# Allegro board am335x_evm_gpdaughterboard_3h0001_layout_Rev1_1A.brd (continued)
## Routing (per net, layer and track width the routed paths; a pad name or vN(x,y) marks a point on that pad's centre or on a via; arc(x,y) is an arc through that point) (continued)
LCD_DATA12: length 169.3
  TOP w0.121: U2.30 v1(114.15,88.94) ; v2(104.33,62.12) U43.T15
  LY3 w0.121: v1(114.85,62.27) 115.03,62.45 115.03,63.08 114.85,63.27 114.85,63.69 114.79,63.75 114.79,65.29 114.98,65.48 114.98,80.57 114.72,80.83 114.72,87.86 114.15,88.43 v1(114.15,88.94)
  LY6 w0.102: 107.86,62.52 105.83,62.52 105.62,62.73 104.94,62.73 v2(104.33,62.12) 104.14,61.93 104.14,61.79 103.93,61.59 103.93,60.88 103.73,60.67 103.73,59.79 103.58,59.64
  LY6 w0.121: 107.86,62.52 109.13,62.52 109.51,62.9 113.58,62.9 114.21,62.27 v1(114.85,62.27) ; v1(34.96,55.79) 36.22,55.79 36.54,55.48 37.7,55.48 38.77,56.55 39.79,56.55 40.69,55.65 44.79,55.65 45.79,56.66 55.64,56.66 56.81,57.82 57.54,57.82 58.41,56.95 62.7,56.95 66.03,53.62 98.58,53.62 99.23,54.27 99.45,54.27 103.58,58.4 103.58,58.61 103.58,59.64
  BOTTOM w0.102: 34.91,81.44 J5.9
  BOTTOM w0.121: v1(34.96,55.79) 34.71,55.54 34.71,46.77 34.84,46.65 35.22,46.65 35.34,46.77 35.34,55.41 35.66,55.72 35.66,70.71 36.2,71.26 38.01,71.26 38.14,71.38 38.14,71.92 38.01,72.05 35.68,72.05 35.37,72.36 35.37,81.04 34.96,81.44 34.91,81.44
LCD_DATA13: length 174.5
  TOP w0.121: v2(103.33,60.13) U43.V14 ; v1(113.75,91.86) U2.29
  LY3 w0.121: v1(114.59,62.9) 114.59,63.6 114.54,63.65 114.54,69.05 113.71,69.88 113.71,89.25 113.75,89.29 v1(113.75,91.86)
  LY6 w0.102: 103.33,59.6 v2(103.33,60.13) 103.33,60.57 103.73,60.96 103.73,61.67 103.93,61.88 103.93,62.28 104.17,62.52 104.3,62.52 104.43,62.65 104.56,62.65 104.94,63.03 104.94,63.29 105.17,63.52 105.5,63.52 105.73,63.29 105.73,63.13 106.13,62.73 107.72,62.73 107.76,62.77 108.74,62.77
  LY6 w0.121: v1(36.74,55.92) 37.51,55.92 39.1,57.5 39.46,57.5 41.05,55.92 44.71,55.92 45.69,56.9 55.54,56.9 56.71,58.08 57.63,58.08 58.51,57.19 62.8,57.19 66.13,53.87 67.33,53.87 67.45,53.99 67.45,54.41 67.56,54.52 67.81,54.52 67.93,54.4 67.93,53.99 68.05,53.87 68.29,53.87 68.41,53.99 68.41,54.52 68.54,54.65 68.77,54.65 68.9,54.52 68.9,53.99 69.02,53.87 69.26,53.87 69.38,53.99 69.38,54.4 69.5,54.52 69.74,54.52 69.86,54.4 69.86,54.27 69.99,54.14 98.75,54.14 99.13,54.52 99.35,54.52 103.33,58.5 103.33,59.6 ; 108.74,62.77 109.38,63.41 114.08,63.41 v1(114.59,62.9)
  BOTTOM w0.102: J6.10 36.61,81.44 36.49,81.32
  BOTTOM w0.121: v1(36.74,55.92) 36.74,57.57 37.05,57.88 37.05,58.46 37.18,58.58 42.71,58.58 42.84,58.71 42.84,62.14 42.71,62.27 37.18,62.27 37.05,62.39 37.05,70.14 37.18,70.26 39.92,70.26 40.04,70.39 40.04,72.05 40.17,72.17 43.73,72.17 43.85,72.3 43.85,73.32 43.73,73.44 43.34,73.44 43.22,73.57 43.22,74.21 43.09,74.33 39.02,74.33 38.95,74.39 36.49,74.39 36.36,74.52 36.36,81.19 36.49,81.32
LCD_DATA14: length 173.4
  TOP w0.121: v1(112.95,91.72) U2.27 ; v2(104.33,60.13) U43.V15
  LY3 w0.121: v1(114.72,61.38) 114.15,61.95 114.15,69.09 113.4,69.84 113.4,78.76 112.75,79.41 112.75,89.25 112.95,89.46 v1(112.95,91.72)
  LY6 w0.102: 107.86,61.38 107.72,61.52 105.94,61.52 105.73,61.73 105.04,61.73 104.74,61.43 104.74,60.97 104.33,60.57 v2(104.33,60.13) 104.33,59.6
  LY6 w0.121: 104.33,59.6 104.33,58.36 99.67,53.69 99.41,53.69 98.84,53.12 65.06,53.12 61.73,56.45 56.77,56.45 56.43,56.11 45.95,56.11 45.51,55.67 45.51,55.67 44.99,55.15 44.58,55.15 44.58,55.16 41.44,55.16 41.31,55.03 41.31,54.52 41.19,54.39 39.98,54.39 39.85,54.52 39.85,55.16 39.72,55.28 39.09,55.28 38.97,55.16 38.97,54.52 38.84,54.39 35.16,54.39 35.04,54.51 35.04,55.16 34.92,55.28 34.68,55.28 34.56,55.16 34.56,54.51 34.44,54.39 34.2,54.39 34.08,54.51 34.08,55.16 33.96,55.28 33.72,55.28 33.59,55.16 33.59,54.51 33.47,54.39 31.15,54.39 31.03,54.52 31.03,55.28 31.15,55.41 v1(32.8,55.41) ; v1(114.72,61.38) 107.86,61.38
  BOTTOM w0.102: J5.12 31.95,80.17 31.69,79.92
  BOTTOM w0.121: 31.69,79.92 31.69,74.08 31.82,73.95 33.44,73.95 33.57,73.82 33.57,73.38 33.69,73.26 34.33,73.26 34.46,73.13 34.46,71.18 34.84,70.81 34.84,68.83 34.71,68.71 34.27,68.71 34.14,68.58 34.14,68.03 34.45,67.71 34.45,67.41 34.14,67.09 34.14,66.73 34.45,66.41 34.45,66.15 34.1,65.79 34.1,65.57 33.97,65.44 31.28,65.44 31.15,65.32 31.15,64.04 31.35,63.84 32.12,63.84 32.68,63.28 34.71,63.28 34.84,63.16 34.84,60.74 34.71,60.62 32.68,60.62 32.55,60.49 32.55,60.11 32.68,59.98 34.71,59.98 34.84,59.85 34.84,58.97 34.71,58.84 32.93,58.84 32.8,58.71 v1(32.8,55.41)
LCD_DATA15: length 169.7
  TOP w0.102: U43.V17 v2(106.34,60.13)
  TOP w0.121: U2.26 112.55,89.06 v1(112.31,88.81)
  LY3 w0.121: v1(112.31,88.81) 112.31,88.18 112.5,87.98 112.5,79.31 113.15,78.66 113.15,69.74 113.9,68.99 113.9,61.84 114.08,61.66 v1(114.08,58.97)
  LY6 w0.102: 107.86,59.6 106.84,59.6 106.34,60.11 ; 105.83,59.09 105.83,59.6 106.34,60.11 ; 106.34,60.11 v2(106.34,60.13)
  LY6 w0.121: v1(114.08,58.97) 111.67,58.97 111.04,59.6 107.86,59.6 ; v1(46.65,54.9) 46.65,54.52 46.77,54.39 56.17,54.39 57.44,55.66 61,55.66 62.27,54.39 62.27,52.9 63.06,52.11 104.3,52.11 105.83,53.63 105.83,59.09
  BOTTOM w0.102: J6.7 39.36,82.71
  BOTTOM w0.121: v1(46.65,54.9) 46.65,53.89 46.77,53.76 49.82,53.76 49.95,53.89 49.95,82.78 49.82,82.91 48.79,82.91 48.66,82.79 48.66,82.59 48.54,82.46 48.31,82.46 48.18,82.59 48.18,82.79 48.06,82.91 47.82,82.91 47.7,82.79 47.7,82.07 47.58,81.95 47.34,81.95 47.22,82.07 47.22,82.79 47.1,82.91 46.86,82.91 46.73,82.79 46.73,82.07 46.61,81.95 46.37,81.95 46.25,82.07 46.25,82.79 46.13,82.91 45.89,82.91 45.77,82.79 45.77,82.07 45.65,81.95 45.41,81.95 45.29,82.07 45.29,82.79 45.17,82.91 44.92,82.91 44.8,82.79 44.8,82.07 44.68,81.95 43.6,81.95 43.47,82.08 43.47,83 42.49,83.98 40.68,83.98 40.55,83.86 40.55,82.97 40.42,82.84 40.17,82.84 40.04,82.97 40.04,85.38 39.92,85.51 39.66,85.51 39.53,85.38 39.53,82.84 39.41,82.71 39.36,82.71
LCD_DEN: length 129.2
  TOP w0.121: v2(99.34,60.13) U43.V10
  LY6 w0.102: v2(99.34,60.13) 99.34,59.97 98.97,59.6
  LY6 w0.121: 98.97,59.6 98.72,59.35 87.03,59.35 86.91,59.47 86.91,59.73 86.78,59.85 86.4,59.85 86.27,59.73 86.27,59.47 86.14,59.35 85.89,59.35 85.76,59.47 85.76,59.73 85.64,59.85 85.39,59.85 85.27,59.73 85.27,59.47 85.15,59.35 84.9,59.35 84.78,59.47 84.78,61 84.66,61.12 84.42,61.12 84.3,61 84.3,59.47 84.18,59.35 83.94,59.35 83.82,59.47 83.82,61 83.7,61.12 83.46,61.12 83.34,61 83.34,59.47 83.22,59.35 82.97,59.35 82.85,59.47 82.85,61 82.73,61.12 82.49,61.12 82.37,61 82.37,59.47 82.25,59.35 82.01,59.35 81.89,59.47 81.89,61 81.77,61.12 81.53,61.12 81.41,61 81.41,59.47 81.29,59.35 81.04,59.35 80.92,59.47 80.92,61 80.8,61.12 80.56,61.12 80.44,61 80.44,60.11 80.31,59.98 80.09,59.98 79.96,60.11 79.96,61 79.84,61.12 50.01,61.12 49.82,61.31 43.98,61.31 43.92,61.25 v1(43.85,61.25)
  BOTTOM w0.102: 39.36,76.36 J6.17
  BOTTOM w0.121: 39.36,76.36 39.79,76.36 39.92,76.24 39.92,74.97 40.04,74.84 41.19,74.84 41.31,74.97 41.31,80.17 41.58,80.44 48.3,80.44 48.42,80.31 48.42,64.68 48.3,64.55 48.05,64.55 47.93,64.67 47.93,66.34 47.81,66.46 47.57,66.46 47.45,66.34 47.45,64.67 47.33,64.55 47.08,64.55 46.96,64.67 46.96,66.34 46.84,66.46 46.6,66.46 46.48,66.34 46.48,64.67 46.36,64.55 46.12,64.55 46,64.67 46,66.34 45.88,66.46 45.64,66.46 45.52,66.34 45.52,64.67 45.4,64.55 45.15,64.55 45.03,64.67 45.03,66.34 44.91,66.46 44.67,66.46 44.55,66.34 44.55,64.67 44.43,64.55 43.98,64.55 43.85,64.43 v1(43.85,61.25)
LCD_HSYNC: length 129
  TOP w0.121: v2(101.34,60.13) U43.V12
  LY6 w0.102: v2(101.34,60.13) 101.34,59.6
  LY6 w0.121: 101.34,59.6 101.34,58.79 100.37,57.83 83.05,57.83 82.5,57.28 82.17,57.28 82.05,57.4 82.05,57.71 81.93,57.83 81.69,57.83 81.56,57.71 81.56,57.4 81.44,57.28 81.2,57.28 81.08,57.4 81.08,57.71 80.96,57.83 80.72,57.83 80.6,57.71 80.6,57.4 80.48,57.28 80.24,57.28 80.12,57.4 80.12,57.71 80,57.83 79.75,57.83 79.63,57.71 79.63,57.4 79.51,57.28 79.27,57.28 79.15,57.4 79.15,57.71 79.03,57.83 78.79,57.83 78.67,57.71 78.67,57.4 78.55,57.28 78.31,57.28 78.19,57.4 78.19,57.71 78.07,57.83 77.82,57.83 77.7,57.71 77.7,57.4 77.58,57.28 77.34,57.28 77.22,57.4 77.22,57.71 77.1,57.83 76.86,57.83 76.74,57.71 76.74,57.4 76.62,57.28 76.38,57.28 76.26,57.4 76.26,57.71 76.14,57.83 75.89,57.83 75.77,57.71 75.77,57.4 75.65,57.28 75.41,57.28 75.29,57.4 75.29,57.71 75.17,57.83 74.93,57.83 74.81,57.71 74.81,57.4 74.69,57.28 74.45,57.28 74.33,57.4 74.33,57.71 74.2,57.83 73.96,57.83 73.84,57.71 73.84,57.4 73.72,57.28 73.48,57.28 73.36,57.4 73.36,57.71 73.24,57.83 73,57.83 72.88,57.71 72.88,57.4 72.76,57.28 64.82,57.28 63.42,58.68 60.01,58.68 59.09,59.6 55.79,59.6 55.66,59.47 55.66,59.13 55.5,58.97 55.32,58.97 55.03,59.26 55.03,59.47 54.9,59.6 47.22,59.6 47.09,59.47 47.09,58.58 46.97,58.46 44.61,58.46 v1(44.36,58.71)
  BOTTOM w0.102: 39.36,75.73 37.88,75.73 J6.18
  BOTTOM w0.121: 39.36,75.73 39.53,75.73 39.66,75.6 39.66,74.71 39.79,74.59 41.43,74.59 41.56,74.71 41.56,79.79 41.97,80.19 48.04,80.19 48.17,80.07 48.17,67.22 48.04,67.09 47.8,67.09 47.67,67.21 47.67,68.49 47.55,68.62 47.32,68.62 47.19,68.49 47.19,67.21 47.07,67.09 46.83,67.09 46.71,67.21 46.71,68.62 46.59,68.74 46.35,68.74 46.23,68.62 46.23,67.21 46.11,67.09 45.86,67.09 45.74,67.21 45.74,68.62 45.62,68.74 45.38,68.74 45.26,68.62 45.26,67.21 45.14,67.09 44.9,67.09 44.78,67.21 44.78,68.62 44.66,68.74 44.42,68.74 44.3,68.62 44.3,67.21 44.18,67.09 43.22,67.09 43.09,66.97 43.09,59.15 43.22,59.03 43.4,59.03 43.53,59.15 43.53,59.73 43.65,59.85 44.23,59.85 44.36,59.73 v1(44.36,58.71)
LCD_PCLK: length 129.1
  TOP w0.121: v2(100.34,60.13) U43.V11
  LY6 w0.102: 100.34,59.6 v2(100.34,60.13)
  LY6 w0.121: 100.34,59.6 100.34,59.03 99.89,58.58 72.68,58.58 72.55,58.71 72.55,60.24 72.43,60.36 72.15,60.36 72.03,60.24 72.03,58.7 71.91,58.58 71.66,58.58 71.54,58.7 71.54,60.24 71.42,60.36 71.18,60.36 71.06,60.24 71.06,58.7 70.94,58.58 70.7,58.58 70.58,58.7 70.58,60.24 70.46,60.36 70.22,60.36 70.1,60.24 70.1,58.7 69.98,58.58 69.73,58.58 69.61,58.7 69.61,60.24 69.49,60.36 69.25,60.36 69.13,60.24 69.13,59.09 69,58.97 68.78,58.97 68.65,59.09 68.65,60.24 68.53,60.36 46.77,60.36 46.58,60.17 44.52,60.17 44.49,60.2 v1(44.49,60.24)
  BOTTOM w0.102: 39.36,77 37.88,77 J6.16
  BOTTOM w0.121: 39.36,77 39.98,77 40.11,76.87 40.11,76.39 40.16,76.34 40.16,75.22 40.29,75.09 40.92,75.09 41.05,75.22 41.05,80.42 41.34,80.71 48.4,80.71 48.69,80.42 48.69,61.89 48.56,61.76 48.04,61.76 47.92,61.89 47.92,64.17 47.79,64.3 47.41,64.3 47.28,64.17 47.28,62.01 47.15,61.89 46.65,61.89 46.52,62.01 46.52,64.17 46.39,64.3 46.01,64.3 45.88,64.17 45.88,62.01 45.76,61.89 45.25,61.89 45.12,62.01 45.12,64.17 45,64.3 44.61,64.3 44.49,64.17 v1(44.49,60.24)
LCD_VSYNC: length 129.1
  TOP w0.121: v2(102.33,60.13) U43.V13
  LY6 w0.102: v2(102.33,60.13) 102.33,59.6
  LY6 w0.121: 102.33,59.6 102.33,58.62 100.27,56.55 97.36,56.55 97.11,56.81 96.88,56.81 96.75,56.68 96.75,56.65 96.63,56.53 96.39,56.53 96.27,56.65 96.27,56.96 96.15,57.08 95.91,57.08 95.79,56.96 95.79,56.65 95.67,56.53 95.42,56.53 95.3,56.65 95.3,56.96 95.18,57.08 94.94,57.08 94.82,56.96 94.82,56.65 94.7,56.53 94.46,56.53 94.34,56.65 94.34,56.96 94.22,57.08 93.98,57.08 93.86,56.96 93.86,56.65 93.74,56.53 93.49,56.53 93.37,56.65 93.37,56.96 93.25,57.08 93.01,57.08 92.89,56.96 92.89,56.65 92.77,56.53 92.53,56.53 92.41,56.65 92.41,56.96 92.29,57.08 92.05,57.08 91.93,56.96 91.93,56.65 91.81,56.53 91.56,56.53 91.44,56.65 91.44,56.96 91.32,57.08 91.08,57.08 90.96,56.96 90.96,56.65 90.84,56.53 90.6,56.53 90.48,56.65 90.48,56.96 90.36,57.08 90.12,57.08 90,56.96 90,56.65 89.87,56.53 89.63,56.53 89.51,56.65 89.51,56.96 89.39,57.08 89.15,57.08 89.03,56.96 89.03,56.65 88.91,56.53 88.67,56.53 88.55,56.65 88.55,56.96 88.43,57.08 88.19,57.08 88.06,56.96 88.06,56.65 87.94,56.53 87.7,56.53 87.58,56.65 87.58,56.96 87.46,57.08 87.22,57.08 87.1,56.96 87.1,56.65 86.98,56.53 86.74,56.53 86.62,56.65 86.62,56.96 86.5,57.08 86.26,57.08 86.13,56.96 86.13,56.65 86.01,56.53 85.77,56.53 85.65,56.65 85.65,56.96 85.53,57.08 85.29,57.08 85.17,56.96 85.17,56.65 85.05,56.53 84.81,56.53 84.69,56.65 84.69,56.96 84.57,57.08 84.32,57.08 84.2,56.96 84.2,56.65 84.08,56.53 83.84,56.53 83.72,56.65 83.72,56.96 83.6,57.08 83.36,57.08 83.24,56.96 83.24,56.65 83.12,56.53 64.51,56.53 63.11,57.94 59.1,57.94 58.2,58.84 56.42,58.84 55.23,57.65 51.73,57.65 51.47,57.9 51.47,58.46 51.09,58.84 48.81,58.84 48.42,58.46 48.42,57.9 48.17,57.65 44.31,57.65 43.73,57.06 41.54,57.06 40.35,58.24 38.56,58.24 37.76,57.44 35.6,57.44 v1(35.22,57.82)
  BOTTOM w0.102: J5.17 34.84,76.36 34.91,76.29
  BOTTOM w0.121: 34.91,76.29 35.12,76.08 35.12,72.26 35.58,71.8 35.98,71.8 36.11,71.67 36.11,71.51 35.75,71.15 35.54,71.15 35.41,71.02 35.41,70.81 35.41,58.78 34.71,58.08 34.71,57.19 34.07,56.55 34.07,47.28 34.2,47.15 34.33,47.15 34.46,47.28 34.46,55.92 34.59,56.05 34.6,56.05 35.22,56.67 v1(35.22,57.82)
LCDA_PIN18: length 5.2
  TOP w0.102: 32.03,76.36 J5.18
  TOP w0.121: 32.03,76.36 31.79,76.12 31.79,73.57 32.42,72.94 R13.2
LCDBD_D0: length 74.3
  TOP w0.121: v2(106.34,63.13) U43.R17
  LY3 w0.102: v2(106.34,63.13) 106.74,62.72 107.41,62.72 107.86,62.27 107.86,61.76
  LY3 w0.121: 107.86,61.76 108.11,61.51 108.11,58.58 107.73,58.2 107.73,37.12 105.19,34.58 105.19,32.93 103.8,31.53 v1(103.8,26.71)
  LY6 w0.121: v1(103.8,26.71) 103.29,26.2 78.78,26.2 77.76,27.22 77.76,28.08 77.88,28.21 78.28,28.21 78.4,28.33 78.4,28.57 78.28,28.69 77.88,28.69 77.76,28.81 77.76,29.05 77.88,29.17 78.28,29.17 78.4,29.29 78.4,29.53 78.28,29.65 77.88,29.65 77.76,29.77 J19.4
LCDBD_D1: length 74.2
  TOP w0.121: v2(105.34,63.13) U43.R16
  LY3 w0.102: 107.73,59.6 107.73,61.38 107.48,61.63 107.23,61.63 106.84,62.01 106.84,62.17 106.5,62.52 105.94,62.52 v2(105.34,63.13)
  LY3 w0.121: 107.73,59.6 107.73,58.84 107.48,58.58 107.48,38.26 106.59,37.38 106.59,36.36 104.94,34.71 104.94,33.06 102.91,31.03 v1(102.91,26.71)
  LY6 w0.095: 78.4,32.17 78.4,33.44
  LY6 w0.121: v1(102.91,26.71) 81.31,26.71 81.19,26.83 81.19,27.48 81.07,27.6 80.83,27.6 80.71,27.48 80.71,26.83 80.59,26.71 78.78,26.71 78.4,27.09 78.4,27.98 78.64,28.22 78.64,29.63 78.4,29.88 78.4,32.17 ; 78.4,33.44 J19.3
LCDBD_D2: length 74.5
  TOP w0.121: v2(106.34,64.13) U43.P17
  LY3 w0.102: 107.86,63.72 106.79,63.72 106.38,64.13 v2(106.34,64.13)
  LY3 w0.121: 107.86,63.72 108.29,63.72 108.88,63.14 108.88,61.76 109.51,61.12 109.51,41.06 108.88,40.42 108.88,37.12 106.97,35.22 106.97,33.95 104.94,31.91 v1(104.94,27.22)
  LY6 w0.121: J19.6 79.03,31.28 83.35,26.96 84.38,26.96 84.5,27.08 84.5,27.23 84.62,27.35 84.86,27.35 84.98,27.23 84.98,27.08 85.1,26.96 85.34,26.96 85.46,27.08 85.46,27.23 85.58,27.35 85.83,27.35 85.95,27.23 85.95,27.08 86.07,26.96 86.31,26.96 86.43,27.08 86.43,27.23 86.55,27.35 86.79,27.35 86.91,27.23 86.91,27.08 87.03,26.96 87.27,26.96 87.39,27.08 87.39,27.23 87.51,27.35 87.76,27.35 87.88,27.23 87.88,27.08 88,26.96 88.24,26.96 88.36,27.08 88.36,27.23 88.48,27.35 88.72,27.35 88.84,27.23 88.84,27.08 88.96,26.96 89.2,26.96 89.32,27.08 89.32,27.23 89.44,27.35 89.69,27.35 89.81,27.23 89.81,27.08 89.93,26.96 90.17,26.96 90.29,27.08 90.29,27.23 90.41,27.35 90.65,27.35 90.77,27.23 90.77,27.08 90.89,26.96 102.15,26.96 102.4,27.22 v1(104.94,27.22)
LCDBD_D3: length 74
  TOP w0.121: v2(105.34,64.13) U43.P16
  LY3 w0.102: 107.86,63.41 107.75,63.52 105.97,63.52 105.37,64.13 v2(105.34,64.13)
  LY3 w0.121: v1(104.43,27.92) 104.43,31.79 106.65,34.01 106.65,35.34 108.23,36.92 108.23,36.98 108.62,37.38 108.62,40.55 109.26,41.19 109.26,60.62 108.62,61.25 108.62,62.9 108.11,63.41 107.86,63.41
  LY6 w0.095: 79.67,32.17 79.67,33.44
  LY6 w0.121: 79.67,32.17 79.67,31.5 83.57,27.6 91.81,27.6 91.93,27.48 91.93,27.33 92.05,27.21 92.3,27.21 92.42,27.33 92.42,27.48 92.54,27.6 92.78,27.6 92.9,27.48 92.9,27.33 93.02,27.21 93.26,27.21 93.38,27.33 93.38,27.48 93.5,27.6 93.74,27.6 93.86,27.48 93.86,27.33 93.98,27.21 94.23,27.21 94.35,27.33 94.35,27.48 94.47,27.6 94.71,27.6 94.83,27.48 94.83,27.33 94.95,27.21 95.19,27.21 95.31,27.33 95.31,27.48 95.43,27.6 95.67,27.6 95.79,27.48 95.79,27.33 95.91,27.21 96.16,27.21 96.28,27.33 96.28,27.48 96.4,27.6 96.64,27.6 96.76,27.48 96.76,27.33 96.88,27.21 97.12,27.21 97.24,27.33 97.24,27.48 97.36,27.6 104.11,27.6 v1(104.43,27.92) ; 79.67,33.44 J19.5
LCDBD_D4: length 74.5
  TOP w0.121: v2(107.34,65.13) U43.N18
  LY3 w0.102: v2(107.34,65.13) 107.86,65.13
  LY3 w0.121: v1(106.34,28.36) 106.34,32.04 110.03,35.73 110.03,40.05 110.82,40.85 110.82,62.73 108.5,65.06 108.11,65.06 108.05,65.13 107.86,65.13
  LY6 w0.121: J19.8 80.3,31.28 83.73,27.85 87.29,27.85 87.41,27.98 87.41,28.23 87.54,28.36 87.96,28.36 88.08,28.24 88.08,27.96 88.2,27.84 88.44,27.84 88.56,27.96 88.56,28.24 88.68,28.36 88.92,28.36 89.04,28.24 89.04,27.96 89.16,27.84 89.4,27.84 89.52,27.96 89.52,28.24 89.64,28.36 89.89,28.36 90.01,28.24 90.01,27.96 90.13,27.84 90.37,27.84 90.49,27.96 90.49,28.24 90.61,28.36 90.85,28.36 90.97,28.24 90.97,27.96 91.09,27.84 91.33,27.84 91.45,27.96 91.45,28.24 91.58,28.36 91.82,28.36 91.94,28.24 91.94,27.96 92.06,27.84 92.3,27.84 92.42,27.96 92.42,28.24 92.54,28.36 v1(106.34,28.36)
LCDBD_D5: length 74.1
  TOP w0.121: v2(106.34,65.13) U43.N17
  LY3 w0.102: 107.86,64.71 107.6,64.71 107.58,64.72 106.82,64.72 106.42,65.13 v2(106.34,65.13)
  LY3 w0.121: v1(105.57,28.99) 105.57,31.79 109.78,35.99 109.78,40.18 110.57,40.98 110.57,62.6 108.47,64.71 107.86,64.71
  LY6 w0.095: 80.94,32.17 80.94,33.44
  LY6 w0.121: v1(105.57,28.99) 105.57,28.73 105.45,28.61 89.77,28.61 89.65,28.73 89.65,29 89.53,29.12 89.29,29.12 89.17,29 89.17,28.73 89.05,28.61 88.81,28.61 88.69,28.73 88.69,29 88.57,29.12 88.33,29.12 88.21,29 88.21,28.73 88.08,28.61 87.41,28.61 87.28,28.73 87.28,29.12 87.15,29.25 86.59,29.25 86.46,29.12 86.46,28.23 86.34,28.1 83.83,28.1 80.94,30.99 80.94,32.17 ; 80.94,33.44 J19.7
LCDBD_D6: length 74.4
  TOP w0.121: v2(105.34,65.13) U43.N16
  LY3 w0.102: 107.75,64.47 107.55,64.47 107.5,64.52 105.86,64.52 105.34,65.05 v2(105.34,65.13)
  LY3 w0.121: 107.75,64.47 107.79,64.43 108.37,64.43 110.27,62.52 110.27,41.03 109.53,40.28 109.53,36.39 v1(108.17,35.03)
  LY6 w0.121: 85.38,38.52 85.38,39.52 85.53,39.67 88.42,39.67 89.19,38.9 97.7,38.9 97.95,38.65 97.95,37.76 98.08,37.63 99.52,37.63 99.64,37.76 99.64,38.14 99.76,38.26 100,38.26 100.12,38.14 100.12,36.48 100.25,36.36 100.49,36.36 100.61,36.48 100.61,38.14 100.73,38.26 100.97,38.26 101.09,38.14 101.09,36.48 101.21,36.36 101.45,36.36 101.57,36.48 101.57,38.14 101.69,38.26 101.93,38.26 102.06,38.14 102.06,36.48 102.18,36.36 102.42,36.36 102.54,36.48 102.54,38.14 102.66,38.26 102.9,38.26 103.02,38.14 103.02,36.48 103.14,36.36 107.99,36.36 108.11,36.23 108.11,35.09 v1(108.17,35.03)
LCDBD_D7: length 74.2
  TOP w0.121: v2(107.34,66.13) U43.M18
  LY3 w0.102: 107.86,66.13 v2(107.34,66.13)
  LY3 w0.121: 107.86,66.13 108.07,66.13 108.11,66.08 108.5,66.08 108.63,65.94 108.7,65.94 111.57,63.07 111.57,40 v1(111.22,39.66)
  LY6 w0.121: v1(111.22,39.66) 110.13,39.66 109.77,39.29 98.71,39.29 98.11,39.89 94.92,39.89 94.8,40.01 94.8,41.19 94.67,41.31 94.44,41.31 94.31,41.19 94.31,40.01 94.19,39.89 93.95,39.89 93.83,40.01 93.83,41.19 93.71,41.31 93.48,41.31 93.35,41.19 93.35,40.01 93.23,39.89 92.99,39.89 92.87,40.01 92.87,41.06 92.75,41.19 92.51,41.19 92.38,41.06 92.38,40.01 92.26,39.89 92.02,39.89 91.9,40.01 91.9,41.06 91.78,41.19 91.54,41.19 91.42,41.06 91.42,40.01 91.3,39.89 91.06,39.89 90.94,40.01 90.94,41.06 90.82,41.19 90.57,41.19 90.45,41.06 90.45,40.01 90.33,39.89 89.7,39.89 88.85,40.74 81.89,40.74 81.57,40.42 81.57,38.52
LCDBD_D8: length 74.5
  TOP w0.121: v2(106.34,66.13) U43.M17
  LY3 w0.102: v2(106.34,66.13) 106.42,66.13 106.81,65.73 107.7,65.73 107.77,65.66 107.86,65.66
  LY3 w0.121: v1(111.04,37.12) 110.78,37.38 110.78,40.04 111.32,40.58 111.32,62.97 108.6,65.69 108.5,65.69 108.5,65.7 107.99,65.7 107.95,65.66 107.86,65.66
  LY6 w0.121: v1(111.04,37.12) 110.53,37.12 110.27,36.87 109.68,36.87 109.56,36.99 109.56,38.4 109.44,38.52 109.2,38.52 109.08,38.4 109.08,36.99 108.96,36.87 108.72,36.87 108.6,36.99 108.6,38.4 108.48,38.52 108.23,38.52 108.11,38.4 108.11,36.99 107.99,36.87 107.75,36.87 107.63,36.99 107.63,38.4 107.51,38.52 107.27,38.52 107.15,38.4 107.15,36.99 107.03,36.87 106.72,36.87 106.46,37.12 106.46,38.23 106.18,38.51 103.35,38.51 103.1,38.77 99.5,38.77 99.15,38.41 98.58,38.41 98.45,38.54 98.45,38.85 97.91,39.39 89.43,39.39 88.66,40.16 83.1,40.16 82.84,39.91 J20.11
LCDBD_D9: length 74.5
  TOP w0.121: v2(105.34,66.13) U43.M16
  LY3 w0.102: v2(105.34,66.13) 105.34,66.06 105.88,65.52 107.57,65.52 107.67,65.42 108.06,65.42 108.08,65.44
  LY3 w0.121: 108.08,65.44 108.5,65.44 111.07,62.87 111.07,40.71 110.27,39.92 110.27,37.12 110.53,36.87 v1(110.53,36.23)
  LY6 w0.121: v1(110.53,36.23) 110.53,36.49 110.4,36.61 106.32,36.61 106.2,36.73 106.2,38.14 106.08,38.26 105.83,38.26 105.71,38.14 105.71,36.73 105.59,36.61 105.35,36.61 105.23,36.73 105.23,38.14 105.11,38.26 104.87,38.26 104.75,38.14 104.75,36.73 104.63,36.61 104.39,36.61 104.27,36.73 104.27,38.14 104.15,38.26 103.9,38.26 103.78,38.14 103.78,36.73 103.66,36.61 103.42,36.61 103.27,36.76 103.27,38.25 103,38.52 99.61,38.52 99.25,38.16 98.47,38.16 98.2,38.43 98.2,38.75 97.8,39.15 89.32,39.15 88.56,39.92 84.62,39.92 84.11,39.41 84.11,38.52
LCDBD_D10: length 74.2
  TOP w0.121: v2(107.34,67.13) U43.L18
  LY3 w0.102: 107.71,67.13 v2(107.34,67.13)
  LY3 w0.121: 107.71,67.13 108.59,67.13 112.31,63.41 112.31,35.73 108.75,32.17 108.75,31.35 108.3,30.9 108.3,28.49 108.17,28.36 107.48,28.36 107.35,28.49 v1(107.35,29.88)
  LY6 w0.121: 81.57,32.8 81.57,31.53 82.78,30.33 107.23,30.33 107.35,30.2 v1(107.35,29.88)
LCDBD_D11: length 74.3
  TOP w0.121: v2(106.34,67.13) U43.L17
  LY3 w0.102: v2(106.34,67.13) 106.78,67.13 107.17,67.52 107.5,67.52 107.5,67.52 107.77,67.52
  LY3 w0.121: v1(109.26,32.04) 112.56,35.34 112.56,63.54 108.58,67.52 107.77,67.52
  LY6 w0.121: v1(109.26,32.04) 112.05,32.04 112.18,32.17 112.18,33.06 112.05,33.18 88.81,33.18 88.68,33.06 88.68,32.04 88.56,31.91 85.51,31.91 85.38,32.04 85.38,32.8
LCDBD_D12: length 74.3
  TOP w0.121: v2(105.34,67.13) U43.L16
  LY3 w0.102: v2(105.34,67.13) 105.78,67.13 106.17,67.52 106.25,67.52 106.47,67.73 107.62,67.73 107.73,67.85
  LY3 w0.121: v1(108.75,30.65) 108.76,30.65 112.8,34.7 112.8,63.67 108.63,67.85 107.73,67.85
  LY6 w0.095: 82.21,32.17 82.21,33.44
  LY6 w0.121: 82.21,33.44 81.57,34.07 ; v1(108.75,30.65) 83.72,30.65 82.21,32.17
LCDBD_D13: length 74.2
  TOP w0.121: v2(107.34,68.13) U43.K18
  LY3 w0.102: 107.86,68.13 v2(107.34,68.13)
  LY3 w0.121: 107.86,68.13 107.91,68.13 108.02,68.24 108.62,68.24 113.05,63.81 113.05,40.44 113.32,40.17 v1(113.32,37.76)
  LY6 w0.095: 82.21,39.15 82.21,37.88
  LY6 w0.121: v1(113.32,37.76) 112.43,37.76 112.31,37.88 112.31,38.65 112.18,38.77 111.67,38.77 111.54,38.65 111.54,37.88 111.42,37.76 111.04,37.76 110.92,37.88 110.92,38.77 110.79,38.9 110.56,38.9 110.43,38.77 110.43,37.88 110.31,37.76 110.02,37.76 109.89,37.88 109.89,38.92 109.77,39.04 98.61,39.04 98.01,39.64 89.53,39.64 88.76,40.41 82.57,40.41 82.21,40.04 82.21,39.15 ; 82.21,37.88 81.57,37.25
LCDBD_D14: length 74.1
  TOP w0.121: v2(106.34,68.13) U43.K17
  LY3 w0.102: 107.86,68.55 106.76,68.55 v2(106.34,68.13)
  LY3 w0.121: 107.86,68.55 108.69,68.55 113.3,63.94 113.3,40.65 113.76,40.19 113.76,32.74 112.18,31.15 v1(110.53,31.15)
  LY6 w0.121: J19.12 82.84,32.04 83.98,30.9 108.11,30.9 108.37,31.15 v1(110.53,31.15)
LCDBD_D15: length 74.5
  TOP w0.121: v2(105.34,68.13) U43.K16
  LY3 w0.102: 107.99,68.87 106.08,68.87 v2(105.34,68.13)
  LY3 w0.121: v1(114.08,41.44) 113.7,41.44 113.55,41.59 113.55,64.96 109.7,68.81 108.44,68.81 108.38,68.87 107.99,68.87
  LY6 w0.121: v1(114.08,41.44) 105.16,41.44 105.04,41.32 105.04,40.8 104.92,40.68 104.68,40.68 104.56,40.8 104.56,41.32 104.44,41.44 104.2,41.44 104.08,41.32 104.08,40.8 103.95,40.68 103.71,40.68 103.59,40.8 103.59,41.32 103.47,41.44 96.56,41.44 96.11,41.89 80.56,41.89 80.3,41.64 J20.7
LCDBD_D16: length 74.4
  TOP w0.121: v2(104.33,63.13) U43.R15
  LY3 w0.102: 104.62,59.6 104.62,59.74 104.74,59.85 104.74,62.53 104.53,62.73 104.53,62.93 v2(104.33,63.13)
  LY3 w0.121: v1(104.62,39.79) 104.62,59.6
  LY6 w0.095: 80.94,39.15 80.94,37.88
  LY6 w0.121: 80.94,39.15 80.94,41.31 81.27,41.64 82.6,41.64 82.72,41.52 82.72,41.11 82.84,40.99 83.08,40.99 83.2,41.11 83.2,41.52 83.33,41.64 83.57,41.64 83.69,41.52 83.69,41.11 83.81,40.99 84.05,40.99 84.17,41.11 84.17,41.52 84.29,41.64 84.53,41.64 84.65,41.52 84.65,41.11 84.77,40.99 85.01,40.99 85.13,41.11 85.13,41.52 85.26,41.64 85.5,41.64 85.62,41.52 85.62,41.11 85.74,40.99 85.98,40.99 86.1,41.11 86.1,41.52 86.22,41.64 86.46,41.64 86.58,41.52 86.58,41.11 86.7,40.99 86.94,40.99 87.07,41.11 87.07,41.52 87.19,41.64 87.43,41.64 87.55,41.52 87.55,41.11 87.67,40.99 87.91,40.99 88.03,41.11 88.03,41.52 88.15,41.64 88.39,41.64 88.51,41.52 88.51,41.11 88.63,40.99 88.87,40.99 89,41.11 89,41.52 89.12,41.64 95.03,41.64 95.16,41.52 95.16,40.3 95.29,40.17 95.92,40.17 96.05,40.3 96.05,40.68 96.18,40.8 98.46,40.8 98.59,40.68 98.59,39.76 98.81,39.54 99.17,39.54 99.3,39.66 99.3,41.07 99.42,41.19 99.66,41.19 99.78,41.07 99.78,39.66 99.9,39.54 100.14,39.54 100.26,39.66 100.26,41.07 100.38,41.19 100.62,41.19 100.74,41.07 100.74,39.66 100.86,39.54 101.1,39.54 101.23,39.66 101.23,41.07 101.35,41.19 101.59,41.19 101.71,41.07 101.71,39.66 101.83,39.54 102.07,39.54 102.19,39.66 102.19,40.93 102.32,41.06 102.55,41.06 102.67,40.93 102.67,39.66 102.79,39.54 103.16,39.54 103.41,39.79 v1(104.62,39.79) ; 80.94,37.88 J20.8
LCDBD_D17: length 74.5
  TOP w0.121: v2(104.33,64.13) U43.P15
  LY3 w0.102: 105.07,59.6 105.07,59.73 104.94,59.85 104.94,62.61 104.74,62.82 104.74,63.72 v2(104.33,64.13)
  LY3 w0.121: v1(105.07,42.39) 105.07,42.71 104.88,42.9 104.88,58.64 105.07,58.83 105.07,59.6
  LY6 w0.121: v1(105.07,42.39) 107.61,42.39 107.73,42.26 107.73,41.95 107.61,41.82 104.44,41.82 104.06,42.2 104.06,42.96 103.93,43.09 102.96,43.09 102.84,42.96 102.84,42.27 102.71,42.14 96.92,42.14 96.68,42.39 92.22,42.39 92.1,42.51 92.1,43.49 91.97,43.61 91.73,43.61 91.61,43.49 91.61,42.51 91.49,42.39 91.25,42.39 91.13,42.51 91.13,43.49 91.01,43.61 90.77,43.61 90.65,43.49 90.65,42.51 90.53,42.39 90.29,42.39 90.16,42.51 90.16,43.49 90.04,43.61 89.8,43.61 89.68,43.49 89.68,42.51 89.56,42.39 89.32,42.39 89.2,42.51 89.2,43.49 89.08,43.61 88.84,43.61 88.72,43.49 88.72,42.51 88.6,42.39 82.33,42.39 82.21,42.51 82.21,43.48 82.08,43.6 77.51,43.6 77.38,43.48 77.38,40.54 77.51,40.42 78.9,40.42 79.03,40.29 J20.5
LCDBD_D18: length 74.5
  TOP w0.121: v2(103.33,64.13) U43.P14
  LY3 w0.102: v2(103.33,64.13) 103.33,63.68 103.73,63.29 103.73,59.79 103.66,59.71 103.66,59.6
  LY3 w0.121: 103.66,59.6 103.66,56.81 103.86,56.61 103.86,54.35 103.87,54.34 103.87,49.32 103.75,49.2 101.63,49.2 101.51,49.08 101.51,48.84 101.63,48.71 103.75,48.71 103.87,48.59 103.87,48.35 103.75,48.23 101.63,48.23 101.51,48.11 101.51,47.87 101.63,47.75 103.75,47.75 103.87,47.63 103.87,47.39 103.75,47.27 101.63,47.27 101.51,47.15 101.51,46.9 101.63,46.78 103.75,46.78 103.87,46.66 103.87,44.31 103.62,44.05 v1(103.62,41.89)
  LY6 w0.095: 79.67,37.88 79.67,39.15
  LY6 w0.121: 79.67,39.15 79.67,40.55 79.54,40.68 77.76,40.68 77.63,40.8 77.63,41.31 77.76,41.44 78.9,41.44 79.03,41.57 79.03,42.58 78.9,42.71 77.76,42.71 77.63,42.84 77.63,43.23 77.76,43.36 81.83,43.36 81.95,43.23 81.95,42.26 82.08,42.14 96.21,42.14 96.45,41.89 v1(103.62,41.89) ; J20.6 79.67,37.88
LCDBD_D19: length 74.4
  TOP w0.121: v2(104.33,65.13) U43.N15
  LY3 w0.102: v2(104.33,65.13) 104.94,64.52 104.94,62.9 105.32,62.52 105.5,62.52 105.73,62.29 105.73,62.24 105.96,62.01 105.96,61.3 105.94,61.29 105.94,59.74 106.08,59.6
  LY3 w0.121: 106.08,59.6 106.08,39.15 104.56,37.63 104.56,33.03 102.66,31.13 102.66,31.03 102.65,31.03 102.65,27.34 102.4,27.09 102.4,24.68 102.27,24.55 102.02,24.55 101.89,24.68 101.89,32.07 102.5,32.68 v1(102.91,32.68)
  LY6 w0.095: 84.75,32.17 84.75,33.44
  LY6 w0.121: 84.75,32.17 84.75,31.79 84.87,31.66 88.81,31.66 88.94,31.79 88.94,32.55 89.06,32.68 v1(102.91,32.68) ; 84.75,33.44 84.11,34.07
LCDBD_D20: length 74.1
  TOP w0.121: v2(103.33,65.13) U43.N14
  LY3 w0.102: v2(103.33,65.13) 103.33,64.68 103.73,64.29 103.73,64.24 103.94,64.03 103.94,59.84 104.18,59.6
  LY3 w0.121: 104.18,59.6 104.18,44.11 104.11,44.04 v1(104.11,43.6)
  LY6 w0.121: v1(104.11,43.6) 104.11,44.74 103.98,44.87 101.76,44.87 101.64,44.74 101.64,43.01 101.51,42.88 101.13,42.88 101,43.01 101,43.98 100.88,44.11 87.71,44.11 87.59,43.99 87.59,43 87.47,42.88 87.23,42.88 87.11,43 87.11,43.99 86.98,44.11 86.74,44.11 86.62,43.99 86.62,43 86.5,42.88 86.26,42.88 86.14,43 86.14,43.99 86.02,44.11 85.78,44.11 85.66,43.99 85.66,43 85.54,42.88 85.3,42.88 85.17,43 85.17,43.99 85.05,44.11 84.81,44.11 84.69,43.99 84.69,43 84.57,42.88 84.33,42.88 84.21,43 84.21,43.99 84.09,44.11 83.85,44.11 83.73,43.99 83.73,43 83.61,42.88 83.35,42.88 83.22,43.01 83.22,43.98 83.1,44.11 75.48,44.11 75.35,43.98 75.35,40.04 75.48,39.92 77.63,39.92 77.76,39.79 J20.3
LCDBD_D21: length 74.2
  TOP w0.121: v2(102.33,65.13) U43.N13
  LY3 w0.102: v2(102.33,65.13) 102.33,64.74 102.74,64.34 102.74,63.57 102.94,63.36 102.94,62.65 102.74,62.45 102.74,59.69 102.65,59.6
  LY3 w0.121: 102.65,59.6 102.6,59.55 102.6,55.63 102.65,55.58 102.65,49.69 102.53,49.57 101,49.57 100.88,49.44 100.88,42.71 101,42.58 v1(102.15,42.58)
  LY6 w0.095: 78.4,39.15 78.4,37.88
  LY6 w0.121: 78.4,39.15 78.4,40.04 78.27,40.17 75.73,40.17 75.6,40.3 75.6,40.54 75.72,40.66 77.01,40.66 77.13,40.78 77.13,41.03 77.01,41.15 75.72,41.15 75.6,41.27 75.6,41.51 75.72,41.63 77.01,41.63 77.13,41.75 77.13,41.99 77.01,42.11 75.72,42.11 75.6,42.23 75.6,42.47 75.72,42.59 77.01,42.59 77.13,42.72 77.13,42.96 77.01,43.08 75.72,43.08 75.6,43.2 75.6,43.73 75.73,43.85 82.33,43.85 82.46,43.73 82.46,42.76 82.59,42.63 88.08,42.63 88.2,42.75 88.2,43.74 88.32,43.86 100.49,43.86 100.62,43.73 100.62,42.58 100.75,42.46 102.02,42.46 v1(102.15,42.58) ; 78.4,37.88 J20.4
LCDBD_D22: length 74.3
  TOP w0.121: v2(104.33,66.13) U43.M15
  LY3 w0.102: 107.86,66.52 105.17,66.52 104.78,66.13 v2(104.33,66.13)
  LY3 w0.121: v1(107.86,32.55) 111.81,36.5 111.81,63.17 108.8,66.18 108.77,66.18 108.43,66.52 107.86,66.52
  LY6 w0.121: v1(107.86,32.55) 106.72,31.41 92.87,31.41 92.75,31.53 92.75,32.3 92.62,32.43 92.37,32.43 92.24,32.3 92.24,31.53 92.11,31.41 91.86,31.41 91.73,31.53 91.73,32.3 91.6,32.43 91.35,32.43 91.22,32.3 91.22,31.53 91.1,31.41 90.84,31.41 90.72,31.53 90.72,32.3 90.59,32.43 90.33,32.43 90.21,32.3 90.21,31.53 90.08,31.41 89.83,31.41 89.7,31.53 89.7,32.3 89.57,32.43 89.32,32.43 89.19,32.3 89.19,31.53 89.06,31.41 84.62,31.41 84.11,31.91 84.11,32.8
LCDBD_D23: length 74.5
  TOP w0.121: v2(103.33,66.13) U43.M14
  LY3 w0.102: 107.81,66.88 107.66,66.72 104.44,66.72 104.24,66.52 104.17,66.52 103.78,66.13 v2(103.33,66.13)
  LY3 w0.121: v1(107.86,31.79) 107.48,31.41 107.48,30.9 107.61,30.77 107.93,30.77 108.05,30.9 108.05,31 108.49,31.44 108.49,32.42 112.06,35.99 112.06,63.28 108.91,66.43 108.9,66.43 108.46,66.88 107.81,66.88
  LY6 w0.095: 83.48,31.79 83.48,33.44
  LY6 w0.121: v1(107.86,31.79) 107.23,31.15 84.11,31.15 83.48,31.79 ; 83.48,33.44 J19.11
LCDBD_DEN: length 74.2
  TOP w0.121: v2(106.34,62.12) U43.T17
  LY3 w0.102: v2(106.34,62.12) 106.35,62.12 106.84,61.63 106.84,59.6
  LY3 w0.121: v1(105.07,35.66) 105.13,35.72 105.13,36.55 107.23,38.65 107.23,59.22 106.84,59.6
  LY6 w0.095: 86.65,38.52 87.29,37.88 87.29,36.36
  LY6 w0.121: v1(105.07,35.66) 105.07,35.72 104.94,35.85 94.29,35.85 94.17,35.97 94.17,37.12 94.04,37.25 93.81,37.25 93.68,37.12 93.68,35.97 93.56,35.85 93.32,35.85 93.2,35.97 93.2,38.14 93.08,38.26 92.84,38.26 92.72,38.14 92.72,35.97 92.6,35.85 92.36,35.85 92.23,35.97 92.23,38.14 92.11,38.26 91.87,38.26 91.75,38.14 91.75,35.97 91.63,35.85 91.39,35.85 91.27,35.97 91.27,38.14 91.15,38.26 90.91,38.26 90.79,38.14 90.79,35.97 90.67,35.85 90.43,35.85 90.3,35.97 90.3,38.14 90.18,38.26 89.94,38.26 89.82,38.14 89.82,35.97 89.7,35.85 89.46,35.85 89.34,35.97 89.34,38.14 89.22,38.26 88.98,38.26 88.86,38.14 88.86,35.97 88.74,35.85 87.79,35.85 87.29,36.36
LCDBD_HSYNC: length 74.5
  TOP w0.121: v2(107.34,63.13) U43.R18
  LY3 w0.102: 107.86,63.13 v2(107.34,63.13)
  LY3 w0.121: 107.86,63.13 108.37,62.62 108.37,60.11 109,59.47 109,41.31 108.37,40.68 108.37,37.63 107.98,37.24 107.98,37.02 105.95,34.99 v1(105.95,34.33)
  LY6 w0.121: 86.65,37.25 86.65,35.72 86.78,35.6 89.7,35.6 89.83,35.47 89.83,34.84 89.95,34.71 91.73,34.71 92.11,34.33 92.68,34.33 92.8,34.45 92.8,35.1 92.92,35.22 93.16,35.22 93.28,35.1 93.28,34.45 93.4,34.33 93.64,34.33 93.76,34.45 93.76,35.1 93.88,35.22 94.12,35.22 94.24,35.1 94.24,34.45 94.37,34.33 94.61,34.33 94.73,34.45 94.73,35.1 94.85,35.22 95.09,35.22 95.21,35.1 95.21,34.45 95.33,34.33 95.57,34.33 95.69,34.45 95.69,35.1 95.81,35.22 96.05,35.22 96.17,35.1 96.17,34.45 96.3,34.33 96.54,34.33 96.66,34.45 96.66,35.1 96.78,35.22 97.02,35.22 97.14,35.1 97.14,34.45 97.26,34.33 97.5,34.33 97.62,34.45 97.62,35.1 97.74,35.22 97.98,35.22 98.11,35.1 98.11,34.45 98.23,34.33 98.47,34.33 98.59,34.45 98.59,35.1 98.71,35.22 98.95,35.22 99.07,35.1 99.07,34.45 99.19,34.33 99.43,34.33 99.55,34.45 99.55,35.1 99.67,35.22 99.91,35.22 100.04,35.1 100.04,34.45 100.16,34.33 100.4,34.33 100.52,34.45 100.52,35.1 100.64,35.22 100.88,35.22 101,35.1 101,34.45 101.12,34.33 101.36,34.33 101.48,34.45 101.48,35.1 101.6,35.22 101.85,35.22 101.97,35.1 101.97,34.45 102.09,34.33 102.33,34.33 102.45,34.45 102.45,35.1 102.57,35.22 102.81,35.22 102.93,35.1 102.93,34.45 103.05,34.33 103.29,34.33 103.41,34.45 103.41,35.1 103.53,35.22 103.78,35.22 103.9,35.1 103.9,34.45 104.02,34.33 104.26,34.33 104.38,34.45 104.38,35.1 104.5,35.22 104.74,35.22 104.86,35.1 104.86,34.45 104.98,34.33 105.22,34.33 105.34,34.45 105.34,35.1 105.46,35.22 105.71,35.22 105.83,35.1 105.83,34.45 v1(105.95,34.33)
LCDBD_PCLK: length 74.2
  TOP w0.121: v2(107.34,64.13) U43.P18
  LY3 w0.102: v2(107.34,64.13) 107.86,64.13
  LY3 w0.121: 107.86,64.13 108.24,64.13 109.13,63.24 109.13,61.89 109.77,61.25 109.77,40.93 109.13,40.3 109.13,36.61 v1(107.48,34.96)
  LY6 w0.095: 86.02,37.88 86.02,39.15
  LY6 w0.121: 85.38,37.25 86.02,37.88 ; v1(107.48,34.96) 107.48,35.98 107.35,36.11 98.78,36.11 98.66,36.23 98.18,36.23 98.06,36.11 97.81,36.11 97.69,36.23 97.69,38.52 97.57,38.65 97.33,38.65 97.21,38.52 97.21,36.23 97.09,36.11 96.85,36.11 96.73,36.23 96.73,38.52 96.6,38.65 96.36,38.65 96.24,38.52 96.24,36.23 96.12,36.11 95.88,36.11 95.76,36.23 95.76,38.52 95.64,38.65 95.4,38.65 95.28,38.52 95.28,36.23 95.16,36.11 94.91,36.11 94.65,36.36 94.65,38.39 94.4,38.65 89.06,38.65 88.3,39.41 86.27,39.41 86.02,39.15
LCDBD_VSYNC: length 74.2
  TOP w0.121: v2(105.34,62.12) U43.T16
  LY3 w0.102: v2(105.34,62.12) 105.7,61.76 105.7,61.32 105.73,61.29 105.73,59.96 105.7,59.93 105.7,59.6
  LY3 w0.121: 105.7,59.6 105.7,58.9 105.76,58.84 105.76,39.59 105.45,39.28 103.92,39.28 103.8,39.15 103.8,33.57 103.54,33.31 102.78,33.31 101.64,32.17 101.64,22.39 101.52,22.26 101.13,22.26 101,22.39 101,33.57 101.13,33.69 v1(102.02,33.69)
  LY6 w0.095: 86.65,35.09 86.65,34.07
  LY6 w0.121: v1(102.02,33.69) 89.83,33.69 89.26,34.26 89.26,35.09 89.13,35.22 86.78,35.22 86.65,35.09
LCDBDA_PIN18: length 2.6
  TOP w0.121: R146.2 86.91,32.55 86.65,32.8
LED0_TRIG: length 114.9
  TOP w0.121: v2(95.34,65.13) U43.N7 ; R137.2 30.56,117.26 Q11.G v1(30.06,118.73)
  LY6 w0.102: v2(95.34,65.13) 94.92,65.13 94.52,65.52 94.38,65.52 93.93,65.96 93.93,67.12 93.54,67.52 90.72,67.52 90.3,67.09 88.81,67.09
  LY6 w0.121: v1(67.79,67.45) 69.4,67.45 69.76,67.09 88.81,67.09
  BOTTOM w0.121: v1(67.79,67.45) 67.79,78.27 67.39,78.67 67.39,81.23 66.9,81.72 66.9,97.56 62.31,102.15 60.74,102.15 58.9,103.99 58.9,113.88 54.83,117.95 30.84,117.95 v1(30.06,118.73)
LED1_TRIG: length 136.5
  TOP w0.121: v2(96.34,65.13) U43.N8 ; v1(30.14,113.7) 30.14,112.75 Q12.G 30.56,112.18 R139.2
  LY3 w0.102: 97.93,59.6 97.93,65.14 97.55,65.52 97.15,65.52 96.75,65.13 v2(96.34,65.13)
  LY3 w0.121: 97.93,59.6 96.9,58.57 96.9,58.57 96.7,58.37 v1(96.7,55.06)
  LY6 w0.121: v1(30.14,113.7) 30.64,113.19 55.8,113.19 58.48,110.51 67.3,110.51 v1(67.79,110.02)
  BOTTOM w0.121: v1(67.79,110.02) 69.01,110.02 69.51,110.51 78.16,110.51 80.89,107.78 80.89,79.89 84.61,76.17 84.61,55.48 85.82,54.27 95.91,54.27 v1(96.7,55.06)
LED2_TRIG: length 163.1
  TOP w0.121: v2(100.34,65.13) U43.N11 ; v1(30.06,108.57) Q13.G 30.56,107.1 R140.2
  LY3 w0.121: v1(50.2,108.11) 50.2,90.07 49.34,89.21 49.34,47.56 v1(49.06,47.28)
  LY6 w0.121: v1(50.2,108.11) 30.52,108.11 v1(30.06,108.57) ; v1(106.52,57.23) 107.28,56.47 107.28,53 103.01,48.74 94.53,48.74 94.02,48.23 91.16,48.23 90.72,47.79 49.6,47.79 49.09,47.28 v1(49.06,47.28)
  BOTTOM w0.102: 102.23,59.6 101.73,60.1 101.73,60.29 101.5,60.52 101.31,60.52 100.73,61.1 100.73,61.29 100.5,61.52 100.31,61.52 99.94,61.89 99.94,64.31 100.34,64.71 v2(100.34,65.13)
  BOTTOM w0.121: v1(106.52,57.23) 106.52,58.37 105.67,59.22 102.61,59.22 102.23,59.6
LED3_TRIG: length 161.2
  TOP w0.121: R141.2 30.56,102.02 Q14.G v1(30.06,103.49) ; v2(101.34,65.13) U43.N12
  LY6 w0.102: 100.97,103.01 100.37,102.4 99.86,102.4 99.25,103.01 99.23,103.01
  LY6 w0.121: v1(30.06,103.49) 30.54,103.01 46.27,103.01 46.81,102.47 75.09,102.47 75.35,102.22 92.56,102.22 93.01,101.76 95.06,101.76 96.52,103.22 98.13,103.22 98.34,103.01 99.22,103.01 99.23,103.01 ; v1(121.72,99.99) 120.83,100.88 113.83,100.88 112.42,102.28 107.95,102.28 106.81,103.42 103.03,103.42 102.65,103.03 101,103.03 100.97,103.01
  BOTTOM w0.102: 106.72,59.6 106.73,59.61 106.73,60.29 106.5,60.52 104.27,60.52 103.73,61.06 103.73,61.29 103.5,61.52 103.27,61.52 102.73,62.06 102.73,62.29 102.5,62.52 102.27,62.52 101.76,63.03 101.76,64.68 101.34,65.11 v2(101.34,65.13)
  BOTTOM w0.121: 106.72,59.6 107.1,59.22 112.81,59.22 113.07,59.47 114.47,59.47 114.54,59.41 115.55,59.41 115.99,59.86 115.99,64.55 115.55,64.99 115.55,69.65 119.14,73.23 119.14,75.63 122.46,78.95 122.46,99.25 v1(121.72,99.99)
LED4_TRIG: length 134
  TOP w0.121: v1(86.52,60.36) 86.02,59.85 56.43,59.85 53.38,62.9 21.81,62.9 v1(21.56,63.16) ; Q15.G 19.13,117.26 R138.2 v1(20.99,117.26) ; v2(94.34,64.13) U43.P6
  LY3 w0.102: 88.81,61.72 90.51,61.72 90.9,62.12 90.9,62.28 91.35,62.72 93.54,62.72 93.93,63.12 93.93,63.32 94.34,63.72 v2(94.34,64.13)
  LY3 w0.121: v1(86.52,60.36) 86.82,60.36 88.18,61.72 88.81,61.72 ; v1(20.99,117.26) 21.56,116.69 v1(21.56,63.16)
LED5_TRIG: length 123.8
  TOP w0.121: Q16.G 19.13,112.18 R142.2 v1(20.99,112.18) ; v2(95.34,64.13) U43.P7
  LY6 w0.102: 88.81,62.53 93.68,62.53 93.93,62.78 93.93,64.32 94.13,64.52 94.52,64.52 94.92,64.13 v2(95.34,64.13)
  LY6 w0.121: v1(23.15,102.71) 45.96,102.71 46.44,102.22 74.74,102.22 v1(78.07,98.89) ; v1(81.57,62.78) 82.02,63.22 83.16,63.22 83.86,62.53 88.81,62.53
  BOTTOM w0.121: v1(20.99,112.18) 23.15,110.02 v1(23.15,102.71) ; v1(78.07,98.89) 78.07,88.98 78.51,88.54 78.51,82.5 80.14,80.87 80.14,75.29 80.88,74.56 80.88,64.4 81.57,63.7 v1(81.57,62.78)
LED6_TRIG: length 140.4
  TOP w0.121: v2(96.34,64.13) U43.P8 ; v1(48.73,52.11) 48.73,54.14 50.19,55.6 v1(80.28,55.6) ; v1(20.99,107.1) R143.2 19.13,107.1 Q17.G
  LY3 w0.102: 88.81,63.73 92.71,63.73 92.94,63.96 92.94,64.29 93.38,64.72 95.29,64.72 95.89,64.13 v2(96.34,64.13)
  LY3 w0.121: 88.81,63.73 86.64,63.73 81.88,58.97 81.88,57.19 v1(80.28,55.6) ; v1(48.73,105.16) v1(48.73,52.11)
  LY6 w0.121: v1(48.73,105.16) 33.3,105.16 31.36,107.1 v1(20.99,107.1)
LED7_TRIG: length 112.9
  TOP w0.121: Q18.G 19.73,102.51 R144.2 v1(21.12,102.02) 21.69,101.44 22.55,101.44 23.44,100.55 23.44,78.36 37.93,63.87 54.38,63.87 57.76,60.5 85.66,60.5 85.96,60.8 87.29,60.8 87.6,61.12 v1(88.3,61.12) ; v2(97.34,64.13) U43.P9
  LY6 w0.102: v2(97.34,64.13) 97.34,63.71 96.93,63.3 96.93,61.5 96.16,60.73 88.81,60.73
  LY6 w0.121: v1(88.3,61.12) 88.68,60.73 88.81,60.73
MMC1_MUXCTRL: length 103.9
  TOP w0.121: v2(93.34,68.13) U43.K5 ; v1(88.68,143.42) 88.81,143.29 R247.1 90.31,143.29 90.46,143.44 U23.24
  LY3 w0.102: v2(93.34,68.13) 93,68.46 88.81,68.46
  LY3 w0.121: 88.81,68.46 82.12,68.46 79.52,71.06 79.52,82.56 78.51,83.57 78.51,101.77 77.77,102.51 77.77,108.51 77.38,108.89 77.38,139.68 78.14,140.44 78.14,142.9 80.44,145.2 87.29,145.2 88.68,143.8 v1(88.68,143.42)
MON_AIN0: length 2
  TOP w0.121: R34.1 36.57,135.51 36.57,133.9
MON_AIN1: length 3.8
  TOP w0.121: J8.3 R35.1
MON_AIN2: length 3.8
  TOP w0.121: J8.7 R38.1
MON_AIN3: length 3.8
  TOP w0.121: J8.9 R40.1
MON_AIN4: length 3.8
  TOP w0.121: R36.2 41.99,133.9
MON_AIN5: length 3.8
  TOP w0.121: R37.2 J8.4
MON_AIN6: length 3.8
  TOP w0.121: R39.2 J8.8
MON_AIN7: length 3.8
  TOP w0.121: R41.2 J8.10
MUXCTRL_I2C1: length 74.4
  TOP w0.121: U10.6 66.53,83.28 66.71,83.1 R26.2 v1(67.35,82.33) 74.44,82.33 74.74,82.03 81.65,82.03 85.47,85.85 91.84,85.85 94.92,88.93 95.86,88.93 95.98,88.81 102.14,88.81 102.99,87.95 114.86,87.95 115.81,87.01 v1(115.81,83.63) ; v2(106.34,74.12) U43.E17
  LY6 w0.102: v2(106.34,74.12) 106.93,74.72 107.65,74.72 107.65,74.76 107.86,74.76
  LY6 w0.121: 107.86,74.76 108.85,74.76 111.01,76.92 111.01,79.52 113.42,81.94 114.37,81.94 v1(115.81,83.63)
MUXCTRL_I2C2: length 92.6
  TOP w0.102: U43.E18 107.62,73.62 107.86,73.38
  TOP w0.121: 107.86,73.38 108.24,73 109.83,73 110.08,73.26 110.08,73.57 110.21,73.7 110.21,73.73 110.71,74.24 115.47,74.24 116.36,75.13 116.36,87.42 115.41,88.37 109.94,88.37 108.74,89.57 94.51,89.57 92.55,87.61 82.87,87.61 79.45,91.03 v1(66.46,91.03) ; U11.6 67.29,78.71 R30.2 v1(67.35,77.89)
  LY3 w0.121: v1(66.46,91.03) 66.9,90.59 66.9,81.95 67.35,81.5 v1(67.35,77.89)
NAND_ADVN_ALE: length 50.9
  TOP w0.121: U5.17 v1(75.82,87.5) ; v1(110.76,83.26) 110.76,84.75 109.3,86.21 97.61,86.21 97.14,85.74 v1(96.56,85.74) ; v2(106.34,75.12) U43.D17
  LY6 w0.102: 107.86,75.53 107.16,75.53 106.75,75.12 v2(106.34,75.12)
  LY6 w0.121: 107.86,75.53 108.28,75.53 110.76,78 v1(110.76,83.26) ; v1(75.82,87.5) 75.82,87.06 76.64,86.24 95.39,86.24 95.88,85.74 v1(96.56,85.74)
NAND_BE0N_CLE: length 56.4
  TOP w0.121: U5.16 v1(75.32,89.74) ; v2(105.34,75.12) U43.D16
  LY3 w0.102: 107.31,75.53 106.16,75.53 105.75,75.12 v2(105.34,75.12)
  LY3 w0.121: v1(108.55,91.46) 108.11,91.02 108.11,78.82 107.74,78.45 107.74,75.96 107.31,75.53
  LY6 w0.121: v1(75.32,89.74) 77.11,87.94 81.47,87.94 82.12,87.3 89.76,87.3 91.02,88.55 103.69,88.55 105.68,90.54 107.63,90.54 v1(108.55,91.46)
NAND_CSN: length 87.7
  TOP w0.121: v1(107.48,104.15) 93.93,104.15 v1(92.87,103.1) U7.48 ; U5.9 v1(71.82,87.5) ; v2(104.33,75.12) U43.D15 ; v1(71.82,103.1) v1(82.21,103.1) U7.25
  LY3 w0.121: v1(107.48,104.15) 107.48,103.22 107.86,102.84 107.86,97.51 107.67,97.32 v1(107.67,79.01) ; v1(71.82,103.1) v1(71.82,87.5)
  LY6 w0.102: v2(104.33,75.12) 104.78,75.12 105.17,75.52 105.29,75.52 105.73,75.96 105.73,76.41 106.05,76.73 107.53,76.73 107.73,76.93 107.73,78.65
  LY6 w0.121: 107.73,78.65 107.73,78.95 v1(107.67,79.01) ; v1(82.21,103.1) v1(92.87,103.1)
  BOTTOM w0.121: R20.1 71.67,87.65 v1(71.82,87.5)
NAND_D0: length 22.1
  TOP w0.121: U5.29 v1(77.32,106.93) 77.77,106.49 91.88,106.49 92.83,107.44 92.83,109.58 92.19,110.21 v1(91.74,110.21) U7.2
NAND_D1: length 17.6
  TOP w0.121: U5.30 v1(76.82,109.17) ; U7.3 v1(91.34,107.56)
  LY6 w0.121: v1(76.82,109.17) 77.27,108.73 90.17,108.73 v1(91.34,107.56)
NAND_D2: length 22.1
  TOP w0.121: U5.31 v1(76.32,106.93) ; U7.5 v1(90.54,107.42)
  LY6 w0.121: v1(90.54,107.42) 89.97,106.84 85.76,106.84 85.07,106.15 74.59,106.15 74.27,106.47 74.27,106.87 74.53,107.12 75.67,107.12 75.86,106.93 v1(76.32,106.93)
NAND_D3: length 20.5
  TOP w0.121: U7.6 v1(90.14,110.53) 88.76,111.9 v1(75.82,111.9) ; U5.32 v1(75.82,109.17)
  LY3 w0.121: v1(75.82,111.9) v1(75.82,109.17)
NAND_D4: length 26.9
  TOP w0.121: U7.8 v1(89.34,110.07) ; U5.41 v1(71.32,106.93)
  LY6 w0.121: v1(71.32,106.93) 71.32,107.02 69.38,108.96 69.38,109.56 71.03,111.22 88.19,111.22 v1(89.34,110.07)
NAND_D5: length 21.4
  TOP w0.121: U7.9 v1(88.94,107.42) ; U5.42 v1(70.82,109.17)
  LY6 w0.121: v1(88.94,107.42) 87.88,108.48 71.51,108.48 v1(70.82,109.17)
NAND_D6: length 26.5
  TOP w0.121: U7.11 v1(88.14,107.56) ; U5.43 v1(70.32,106.93)
  LY6 w0.121: v1(70.32,106.93) 70.32,106.59 70.83,106.08 74.21,106.08 74.45,105.84 81.5,105.84 81.76,105.57 v1(82.21,105.57)
  BOTTOM w0.121: v1(88.14,107.56) 88.14,105.98 88.58,105.54 88.58,104.16 88.33,103.91 87.87,103.91 86.98,104.8 86.98,105.51 86.47,106.02 82.65,106.02 v1(82.21,105.57)
NAND_D7: length 21.7
  TOP w0.121: U7.12 v1(87.74,110.07) ; U5.44 v1(69.82,109.17)
  LY6 w0.121: v1(69.82,109.17) 69.82,109.63 71.16,110.97 86.84,110.97 v1(87.74,110.07)
NAND_D8: length 12.1
  TOP w0.121: U7.13 v1(87.34,107.42) 86.9,106.97 82.73,106.97 80.54,109.17 v1(78.82,109.17) U5.26
NAND_D9: length 28.5
  TOP w0.121: U5.27 v1(78.32,106.93) ; U7.14 v1(86.94,110.21) ; v1(87.03,117.17) v1(78.32,117.17)
  LY3 w0.121: v1(78.32,117.17) v1(78.32,106.93)
  BOTTOM w0.121: v1(86.94,110.21) 86.94,110.66 87.03,110.75 v1(87.03,117.17)
NAND_D10: length 11.1
  TOP w0.121: U5.28 v1(77.82,109.17) ; U7.16 v1(86.14,110.07)
  LY6 w0.121: v1(77.82,109.17) 78.26,109.61 85.68,109.61 v1(86.14,110.07)
NAND_D11: length 13.7
  TOP w0.121: U7.17 v1(85.74,107.42) ; U5.33 v1(75.32,106.59)
  LY6 w0.121: v1(75.32,106.59) 75.76,106.59 75.86,106.49 80.74,106.49 80.94,106.69 85.01,106.69 v1(85.74,107.42)
NAND_D12: length 20.6
  TOP w0.121: U5.40 v1(71.82,109.17) ; U7.19 v1(84.94,107.56)
  LY3 w0.121: v1(71.82,105.09) v1(71.82,109.17)
  LY6 w0.121: v1(84.94,107.56) 84.31,106.93 v1(80.45,106.93)
  BOTTOM w0.121: v1(80.45,106.93) 78.61,105.09 v1(71.82,105.09)
NAND_D13: length 20.9
  TOP w0.121: U5.45 v1(69.32,106.93) ; U7.20 v1(84.54,110.27)
  LY6 w0.121: v1(71.07,110.03) 71.76,110.71 84.1,110.71 v1(84.54,110.27)
  BOTTOM w0.121: v1(69.32,106.93) 69.32,109.33 70.02,110.03 v1(71.07,110.03)
NAND_D14: length 18.2
  TOP w0.121: U7.22 v1(83.74,110.21) 83.3,110.66 70.31,110.66 v1(68.82,109.17) U5.46
NAND_D15: length 18.6
  TOP w0.121: U7.23 v1(83.34,107.56) ; U5.47 v1(68.32,106.93)
  LY6 w0.121: v1(68.32,106.93) 68.76,107.37 70.51,107.37 70.77,107.12 70.77,106.81 71.08,106.49 71.56,106.49 72.63,107.56 v1(83.34,107.56)
NAND_OEN: length 95.1
  TOP w0.121: v2(106.34,76.13) U43.C17 ; U7.1 v1(92.14,107.42) ; U5.8 v1(71.32,90.08) ; U7.24 v1(82.94,110.07) v1(74.27,110.07)
  LY3 w0.121: v1(107.7,107.42) 107.7,106.21 108.11,105.8 v1(108.11,96.91) ; v1(92.14,107.42) 90.81,108.74 84.27,108.74 v1(82.94,110.07)
  LY6 w0.121: v1(107.7,107.42) v1(92.14,107.42)
  BOTTOM w0.102: v2(106.34,76.13) 106.93,76.72 106.93,77.29 107.16,77.52 107.85,77.52 107.86,77.51
  BOTTOM w0.121: v1(108.11,96.91) 109.01,96 109.01,90.47 108.37,89.83 108.37,78.14 108.11,77.88 108.11,77.63 107.99,77.51 107.86,77.51 ; v1(71.32,90.08) 71.32,105.27 71.83,105.78 73.64,105.78 74.27,106.41 v1(74.27,110.07)
NAND_WAIT: length 54.9
  TOP w0.121: U5.7 v1(70.82,87.5) 71.91,86.41 91.84,86.41 94.67,89.24 96.17,89.24 96.29,89.12 v1(107.15,89.12) ; v2(105.34,76.13) U43.C16
  LY3 w0.102: 106.78,78.65 106.78,76.94 106.46,76.62 105.83,76.62 v2(105.34,76.13)
  LY3 w0.121: 106.78,78.65 106.78,88.31 107.15,88.68 v1(107.15,89.12)
  BOTTOM w0.121: v1(70.82,87.5) 70.4,87.92 R18.1
NAND_WEN: length 85
  TOP w0.102: U43.D18 107.86,74.62
  TOP w0.121: v1(90.69,100.66) 89.36,99.33 v1(76.32,99.33) ; v1(90.66,92.75) 90.97,93.06 93.81,93.06 96.28,90.59 100.24,90.59 100.67,91.02 v1(111.65,91.02) ; v1(115.92,75.37) 115.07,74.53 110.39,74.53 109.92,74.99 108.24,74.99 107.87,74.62 107.86,74.62 ; U5.18 v1(76.32,90.21)
  LY3 w0.121: v1(76.32,99.33) v1(76.32,90.21)
  BOTTOM w0.121: v1(90.66,92.75) 91.47,93.56 91.63,93.56 92.58,94.51 92.58,99.21 91.13,100.66 v1(90.69,100.66) ; v1(111.65,91.02) 112.75,89.92 112.75,85.25 115.92,82.08 v1(115.92,75.37)
NAND_WPN: length 58.6
  TOP w0.121: v2(103.33,74.12) U43.E14 ; U5.19 v1(76.82,87.5)
  LY3 w0.121: v1(111.26,84.52) v1(111.26,89.22)
  LY6 w0.102: 106.94,78.65 106.94,78.15 106.37,77.58 106.17,77.58 105.73,77.13 105.73,76.96 105.49,76.72 105.31,76.72 104.93,76.34 104.93,75.88 104.57,75.52 104.13,75.52 103.73,75.12 103.73,74.96 103.33,74.57 v2(103.33,74.12)
  LY6 w0.121: 106.94,78.65 106.94,78.96 107.51,79.53 109.45,79.53 109.95,80.04 109.95,83.92 110.55,84.52 v1(111.26,84.52) ; v1(111.26,89.22) 109.4,89.22 108.13,87.95 91.06,87.95 90.09,86.98 81.74,86.98 81.23,87.5 v1(76.82,87.5)
  BOTTOM w0.121: R19.1 76.75,87.57 v1(76.82,87.5)
NOR_A0: length 23.8
  TOP w0.121: R250.1 100.93,92.24 102.14,93.45 120.12,93.45 120.95,94.28 U2.2
NOR_A1: length 29.1
  TOP w0.121: U2.3 120.55,94.64 v1(119.8,93.89) ; v2(101.15,101.97) U3.E2
  LY6 w0.102: 102.59,94.21 102.45,94.35 102.45,99.43 101.64,100.24 101.64,101.48 v2(101.15,101.97)
  LY6 w0.121: v1(119.8,93.89) 119.65,93.89 119.49,93.72 103.07,93.72 102.59,94.21
NOR_A2: length 27.1
  TOP w0.121: v2(103.15,101.97) U3.D2 ; v1(119.75,94.83) U2.5
  LY6 w0.102: v2(103.15,101.97) 102.65,101.48 102.65,94.73 103.18,94.21
  LY6 w0.121: v1(119.75,94.83) 119.02,94.1 103.29,94.1 103.18,94.21
NOR_A3: length 20.2
  TOP w0.121: v1(119.35,97.61) 119.35,97.6 U2.6 ; v2(104.15,101.97) U3.C2
  LY6 w0.121: v1(119.35,97.61) 118.92,98.04 118.92,98.62 118.66,98.88 117.72,98.88 116.37,100.23 110.67,100.23 110.1,100.79 108.71,100.79 106.72,102.78 104.96,102.78 v2(104.15,101.97)
NOR_A4: length 16.5
  TOP w0.121: v2(106.14,101.97) U3.A2 ; v1(118.5,97.6) 118.55,97.55 U2.8
  LY6 w0.121: v2(106.14,101.97) 106.73,101.97 108.41,100.29 109.42,100.29 109.98,99.73 116.17,99.73 117.13,98.77 117.13,98.59 118.12,97.6 v1(118.5,97.6)
NOR_A5: length 18.5
  TOP w0.121: v1(118.48,98.44) 118.02,97.98 118.02,97.29 118.15,97.16 U2.9 ; v2(105.15,101.97) U3.B2
  LY6 w0.121: v2(105.15,101.97) 105.7,102.53 106.59,102.53 108.57,100.54 109.52,100.54 110.08,99.98 116.27,99.98 117.81,98.44 v1(118.48,98.44)
NOR_A6: length 18.4
  TOP w0.121: U2.11 117.35,97.34 117.08,97.61 117.08,98.11 v1(116.52,98.67) ; v2(103.15,100.97) U3.D3
  LY6 w0.102: v2(103.15,100.97) 103.15,100.99 103.73,101.57 106.79,101.57
  LY6 w0.121: v1(116.52,98.67) 115.71,99.48 109.88,99.48 109.31,100.05 108.31,100.05 106.79,101.57
NOR_A7: length 16.6
  TOP w0.121: U2.12 116.95,97.09 116.56,97.48 v1(116.56,97.8) ; v2(104.15,100.97) U3.C3
  LY6 w0.102: 107.5,100.17 106.31,101.36 104.54,101.36 v2(104.15,100.97)
  LY6 w0.121: 107.5,100.17 108.51,99.16 113,99.16 113.98,98.19 116.17,98.19 v1(116.56,97.8)
NOR_A8: length 23.5
  TOP w0.121: U4.2 120.95,107.63 120.08,106.76 119,106.76 117.97,105.73 v1(105.51,105.73) ; v2(106.14,100.97) U3.A3
  LY3 w0.102: 105.86,103.01 106.59,102.27 106.59,101.42 v2(106.14,100.97)
  LY3 w0.121: v1(105.51,105.73) 105.51,103.35 105.86,103.01
